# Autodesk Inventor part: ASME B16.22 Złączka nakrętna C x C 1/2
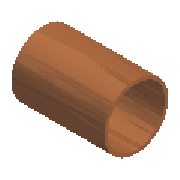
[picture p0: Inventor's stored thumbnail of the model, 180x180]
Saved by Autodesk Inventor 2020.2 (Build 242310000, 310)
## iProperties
Manager: www.cadconsulting.pl
Company: Fabian Stasiak CAD Consulting
NAME: PIPING: ASME B16.22 Coupling C x C
DATA: <meta><inlinegroups number="1" deflen="1.9304"></inlinegroups><connections number="2"></connections><angles><a>3.14159265358979</a></angles></meta>
IsCustomPart: 0
Created: 2014-02
Part Number: ASME B16.22 Złączka nakrętna C x C 1/2
Material: Miedź kuta
Description: Złączka nakrętna
Document SubType Name: Modeling
Standard: ASME B16.22
Designer: F.Stasiak
Standard Revision: 2001
Standards Organization: ANSI
Language: pl-PL
Size Designation: 1/2
Categories: <MemberInstance><Categories><Category DisplayName="Rury cienko- i grubościenne" InternalName="4347fa0f-2144-441d-94cd-e3e15c92b736" Mnemonic="TUBEANDPIPE"><Cate
Density: 1 g/cm^3
Appearance: Miedź - satynowa
Catalog Web Link: www.expertbooks.pl
Author: F.Stasiak
Subject: Zbiór ćwiczeń. Autodesk Inventor 2020. Kurs Professional
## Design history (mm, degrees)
sketch "Sketch1"
  geometry: L1 (0, 0)-(-25.4, 0); L2 (0, 0)-(0, 8.014); L3 (-25.4, 0)-(-25.4, 8.014); L4 (0, 8.014)-(0, 8.75); L5 (0, 8.75)-(-25.4, 8.75); L6 (-25.4, 8.75)-(-25.4, 8.014); L7 (-25.4, 8.014)-(0, 8.014); L8 (-12.7, 8.014)-(-12.7, 0); 1 further point
  constraints: 16 end point, 4 perpendicular, 2 midpoint, 2 parallel, 1 coincident, 1 horizontal
  dimensions: "d0" = 0.7366 distance of L2.end L4.end (= T); "d1" = 8.0137 distance of L1.start L2.end (= 0.5 x F1); "d2" = 25.4 distance of L3.end L2.end (= 2 x G)
revolve "Revolve1" sketch "Sketch1" stored, may be unused: angle "d7" = 90 deg
workpoint "Work Point1"
workaxis "Work Axis1"
workpoint "Work Point2"
workaxis "Work Axis2"
workpoint "Work Point3"
workpoint "Work Point4"
body "Solid1"
other parameters: "G" = 12.7 [user parameter; used in 1 equation term], "T" = 0.7366 [user parameter; used in 1 equation term], "F1" = 16.0274 [user parameter; used in 1 equation term], "Size_Designation" = 5 [user parameter]
